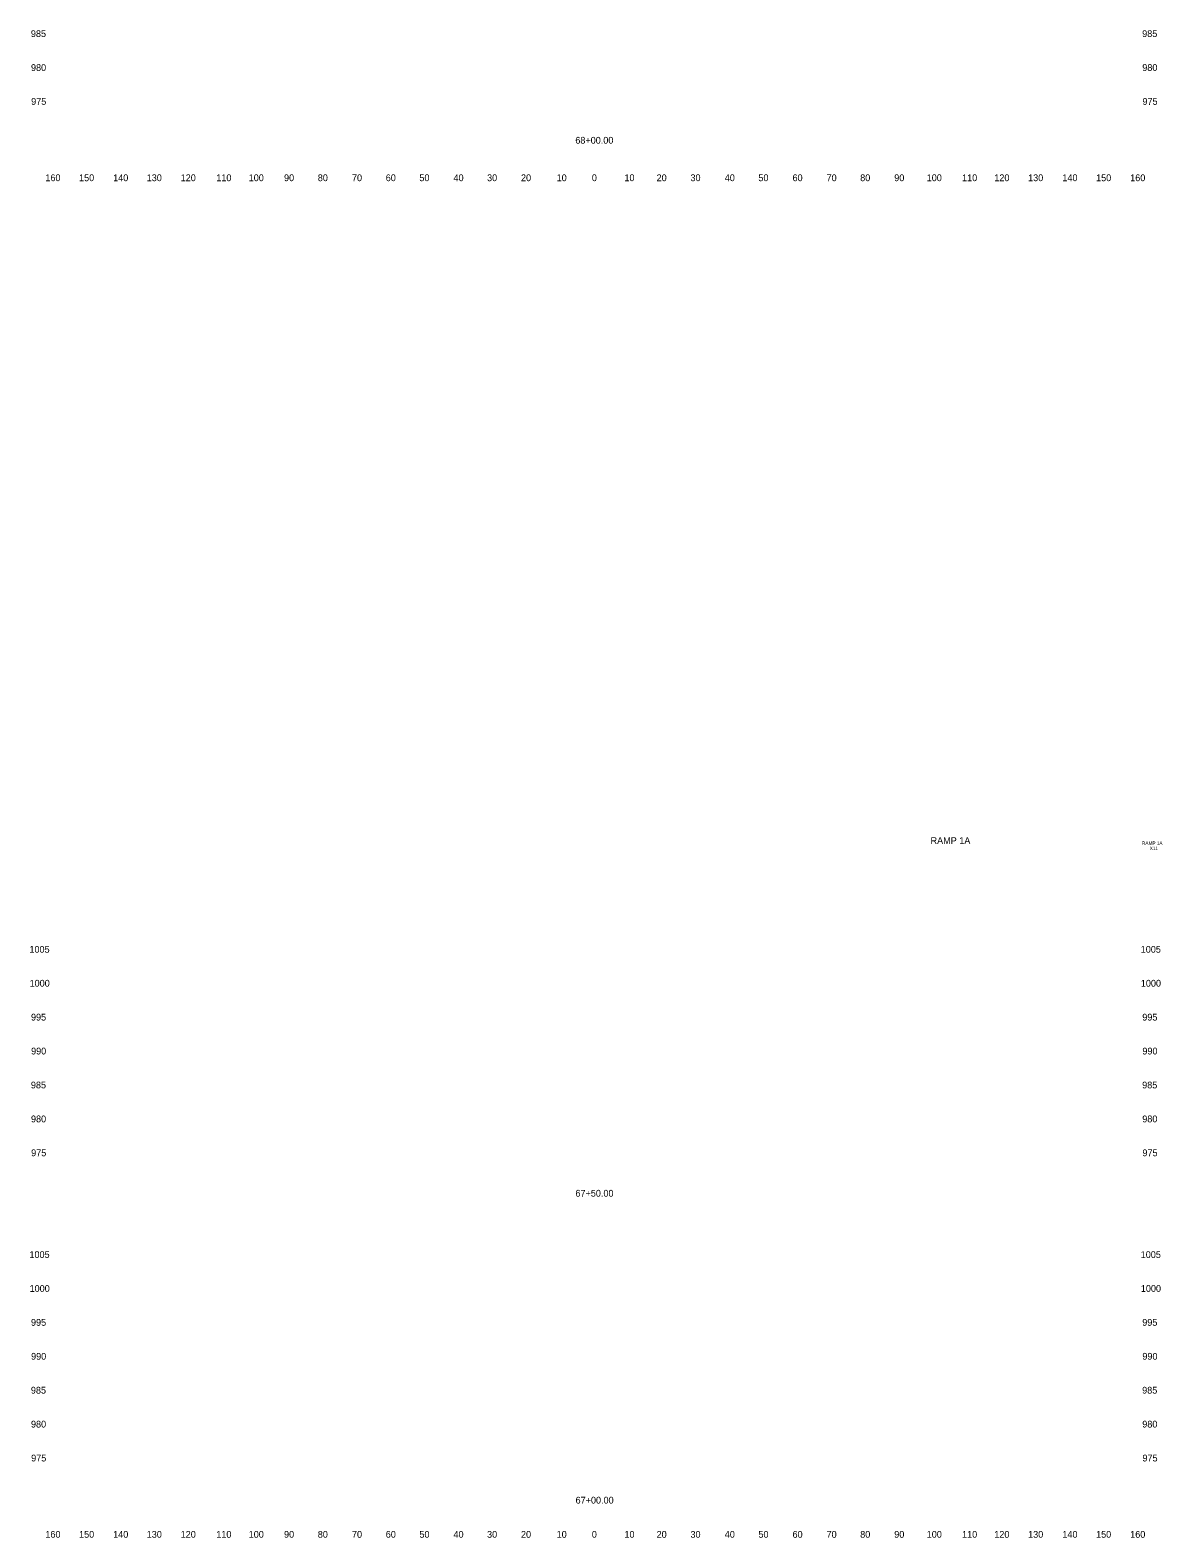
# Model space of a CAD drawing. Extents: x 4994 to 6873, y 4997 to 8804.
# Drawn here: x 5508.6 to 5842.4, y 4997.5 to 5442 of the extents above; entities that cross this region are included whole.
import ezdxf

# ---------------------------------------------------------------- set-up
doc = ezdxf.new("R2010")
doc.units = 0
for name, color, linetype in [('RD_SHT_ID', 7, 'Continuous'), ('RD_XS_TX_Offset', 7, 'Continuous'), ('RD_XS_TX_Station', 7, 'Continuous')]:
    doc.layers.add(name, color=color, linetype=linetype)

msp = doc.modelspace()

# ---------------------------------------------------------------- texts
at = {"layer": 'RD_SHT_ID'}
for s, height, p in [('RAMP 1A', 2, (5774.21, 5202.06)), ('RAMP 1A', 1, (5836.57, 5201.8)), ('X11', 1, (5838.85, 5200.3))]:
    msp.add_text(s, height=height, dxfattribs=at).set_placement(p)
at = {"layer": 'RD_XS_TX_Offset'}
for s, p in [('985', (5508.83, 5440)), ('985', (5836.63, 5440)), ('980', (5508.86, 5430)), ('980', (5836.66, 5430)), ('975', (5508.91, 5420)), ('975', (5836.71, 5420)), ('160', (5513.1, 5397.5)), ('150', (5523.04, 5397.5)), ('140', (5533.1, 5397.5)), ('130', (5542.99, 5397.5)), ('120', (5553.01, 5397.5)), ('110', (5563.51, 5397.5)), ('100', (5573.07, 5397.5)), ('90', (5583.5, 5397.5)), ('80', (5593.46, 5397.5)), ('70', (5603.54, 5397.5)), ('60', (5613.5, 5397.5)), ('50', (5623.43, 5397.5)), ('40', (5633.5, 5397.5)), ('30', (5643.39, 5397.5)), ('20', (5653.4, 5397.5)), ('10', (5663.91, 5397.5)), ('0', (5674.3, 5397.5)), ('0', (5674.3, 5397.5)), ('10', (5683.91, 5397.5)), ('20', (5693.4, 5397.5)), ('30', (5703.39, 5397.5)), ('40', (5713.5, 5397.5)), ('50', (5723.43, 5397.5)), ('60', (5733.5, 5397.5)), ('70', (5743.54, 5397.5)), ('80', (5753.46, 5397.5)), ('90', (5763.5, 5397.5)), ('100', (5773.07, 5397.5)), ('110', (5783.51, 5397.5)), ('120', (5793.01, 5397.5)), ('130', (5802.99, 5397.5)), ('140', (5813.1, 5397.5)), ('150', (5823.04, 5397.5)), ('160', (5833.1, 5397.5)), ('1005', (5508.4, 5170)), ('1005', (5836.2, 5170)), ('1000', (5508.44, 5160)), ('1000', (5836.24, 5160)), ('995', (5508.86, 5150)), ('995', (5836.66, 5150)), ('990', (5508.89, 5140)), ('990', (5836.69, 5140)), ('985', (5508.83, 5130)), ('985', (5836.63, 5130)), ('980', (5508.86, 5120)), ('980', (5836.66, 5120)), ('975', (5508.91, 5110)), ('975', (5836.71, 5110)), ('1005', (5508.4, 5080)), ('1005', (5836.2, 5080)), ('1000', (5508.44, 5070)), ('1000', (5836.24, 5070)), ('995', (5508.86, 5060)), ('995', (5836.66, 5060)), ('990', (5508.89, 5050)), ('990', (5836.69, 5050)), ('985', (5508.83, 5040)), ('985', (5836.63, 5040)), ('980', (5508.86, 5030)), ('980', (5836.66, 5030)), ('975', (5508.91, 5020)), ('975', (5836.71, 5020)), ('160', (5513.1, 4997.5)), ('150', (5523.04, 4997.5)), ('140', (5533.1, 4997.5)), ('130', (5542.99, 4997.5)), ('120', (5553.01, 4997.5)), ('110', (5563.51, 4997.5)), ('100', (5573.07, 4997.5)), ('90', (5583.5, 4997.5)), ('80', (5593.46, 4997.5)), ('70', (5603.54, 4997.5)), ('60', (5613.5, 4997.5)), ('50', (5623.43, 4997.5)), ('40', (5633.5, 4997.5)), ('30', (5643.39, 4997.5)), ('20', (5653.4, 4997.5)), ('10', (5663.91, 4997.5)), ('0', (5674.3, 4997.5)), ('0', (5674.3, 4997.5)), ('10', (5683.91, 4997.5)), ('20', (5693.4, 4997.5)), ('30', (5703.39, 4997.5)), ('40', (5713.5, 4997.5)), ('50', (5723.43, 4997.5)), ('60', (5733.5, 4997.5)), ('70', (5743.54, 4997.5)), ('80', (5753.46, 4997.5)), ('90', (5763.5, 4997.5)), ('100', (5773.07, 4997.5)), ('110', (5783.51, 4997.5)), ('120', (5793.01, 4997.5)), ('130', (5802.99, 4997.5)), ('140', (5813.1, 4997.5)), ('150', (5823.04, 4997.5)), ('160', (5833.1, 4997.5))]:
    msp.add_text(s, height=2, dxfattribs=at).set_placement(p)
at = {"layer": 'RD_XS_TX_Station'}
for s, p in [('68+00.00', (5669.42, 5408.56)), ('67+50.00', (5669.46, 5098.08)), ('67+00.00', (5669.5, 5007.58))]:
    msp.add_text(s, height=2, dxfattribs=at).set_placement(p)

doc.saveas('drawing.dxf')
